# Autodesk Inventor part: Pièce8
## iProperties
Shininess: 64.0
Length Units: 11269
Angle Units: 11279
Time Units: 11290
Mass Units: 11283
Length Display Precision: 3
Angle Display Precision: 2
Compacted: True
Part Number: Pièce8
Document SubType Name: Modeling
Created: 2004-06
Material: Par défaut
Designer: administrateur
Density: 0.0
Volumn: 0.0
Area: 0.0
PropertySet Name: Model Information
Control State: 0
Master: False
Checked Out: False
Author: administrateur
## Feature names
1. Extrusion1
2. Extrusion2
3. Extrusion3
4. Balayage2
5. Réseau rectangulaire2 [Rectangular Pattern]
